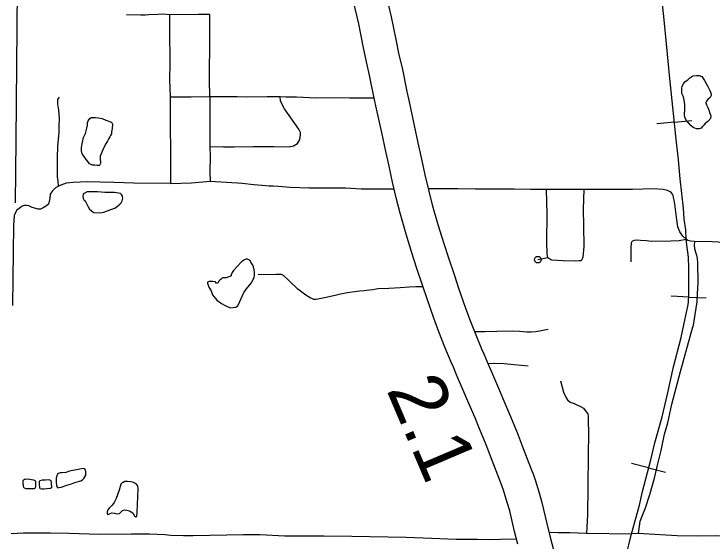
# Model space of a CAD drawing. Extents: x 61396 to 64680, y 55472 to 57605.
# Drawn here: x 62618.7 to 62782.6, y 56206.3 to 56330.1 of the extents above; entities that cross this region are included whole.
import ezdxf

# ---------------------------------------------------------------- set-up
doc = ezdxf.new("R2010")
doc.units = 0
for name, color, linetype in [('15', 7, 'Continuous'), ('33', 7, 'Continuous'), ('34', 7, 'Continuous'), ('35', 7, 'Continuous'), ('40', 7, 'Continuous'), ('48', 7, 'Continuous'), ('6', 7, 'Continuous')]:
    doc.layers.add(name, color=color, linetype=linetype)

msp = doc.modelspace()

# ---------------------------------------------------------------- linework, layer by layer
at = {"layer": '15'}
for points in [[(62706.06, 56334.76), (62707.32, 56329.4), (62708.41, 56324.06), (62709.1, 56320.51), (62709.85, 56317.42), (62710.97, 56311.87), (62711.49, 56309.45), (62712.72, 56303.87), (62713.58, 56299.82), (62714.43, 56295.95), (62715.19, 56292.28), (62716.07, 56288.8), (62716.93, 56285.29), (62718.28, 56280.6), (62719.64, 56276.15), (62720.67, 56273.01), (62722.16, 56268.65), (62723.13, 56265.69), (62724.66, 56261.25), (62725.77, 56258.25), (62727.17, 56254.77), (62728.54, 56251.45), (62729.08, 56250.26), (62729.86, 56248.39), (62731.57, 56244.37), (62732.49, 56242.23), (62734.18, 56238.3), (62735.11, 56236.08), (62736.87, 56231.81), (62738.31, 56228.06), (62740.19, 56223.16), (62740.69, 56221.86), (62741.12, 56220.66), (62742.02, 56217.63), (62742.71, 56215.39), (62743.83, 56210.41), (62744.58, 56207.56), (62745.86, 56202.44)], [(62737.02, 56205.61), (62736.24, 56208.55), (62735.16, 56213.38), (62734.54, 56215.37), (62733.69, 56218.24), (62733.37, 56219.15), (62732.9, 56220.35), (62731.02, 56225.26), (62729.61, 56228.92), (62727.9, 56233.08), (62726.99, 56235.24), (62725.31, 56239.15), (62724.38, 56241.31), (62722.67, 56245.35), (62721.92, 56247.12), (62721.37, 56248.34), (62719.93, 56251.82), (62718.48, 56255.44), (62717.3, 56258.62), (62715.72, 56263.21), (62714.75, 56266.17), (62713.27, 56270.53), (62712.19, 56273.79), (62710.79, 56278.37), (62709.38, 56283.28), (62708.49, 56286.91), (62707.57, 56290.54), (62706.79, 56294.32), (62705.94, 56298.17), (62705.08, 56302.23), (62703.86, 56307.79), (62703.32, 56310.27), (62702.22, 56315.73), (62701.47, 56318.86), (62700.75, 56322.54), (62699.69, 56327.72), (62698.46, 56332.97)]]:
    msp.add_lwpolyline(points, dxfattribs=at)
at = {"layer": '33'}
for p, q in [((62655.5, 56290.3), (62646.86, 56290.34)), ((62744.09, 56272.82), (62741.72, 56272.38)), ((62753.18, 56208.16), (62763.74, 56208)), ((62753.18, 56208.16), (62753.18, 56208.16)), ((62765.34, 56208.05), (62763.74, 56208))]:
    msp.add_line(p, q, dxfattribs=at)
for points in [[(62655.24, 56329.88), (62654.52, 56329.98), (62653.5, 56330.04), (62652.47, 56329.98), (62650.42, 56329.84), (62649.6, 56329.78), (62648.54, 56329.81), (62645.14, 56329.84)], [(62664.68, 56329.97), (62661.98, 56329.93), (62655.24, 56329.88)], [(62655.24, 56329.88), (62655.27, 56326.46), (62655.3, 56318.45), (62655.25, 56314.72), (62655.39, 56310.61)], [(62664.71, 56310.73), (62664.61, 56314.54), (62664.72, 56324.6), (62664.68, 56329.97)], [(62655.39, 56310.61), (62657.57, 56310.61), (62660.35, 56310.59), (62664.71, 56310.73)], [(62655.39, 56310.61), (62655.39, 56308.77), (62655.39, 56306.03), (62655.39, 56302.65), (62655.46, 56299.01), (62655.5, 56290.3)], [(62664.71, 56310.73), (62664.74, 56305.92), (62664.71, 56298.99)], [(62664.71, 56310.73), (62666.68, 56310.67), (62671.1, 56310.69), (62673.67, 56310.64), (62678.19, 56310.69), (62681.26, 56310.72)], [(62664.71, 56298.99), (62667.91, 56298.85), (62670.43, 56298.9), (62674.98, 56298.95), (62679.75, 56298.93), (62683.3, 56298.85), (62684.39, 56299.08), (62685.29, 56299.67), (62685.85, 56300.56), (62686.03, 56301.66), (62686.03, 56302.24), (62685.59, 56303.06), (62682.25, 56307.76), (62681.33, 56309.59), (62681.26, 56310.72)], [(62681.26, 56310.72), (62682.55, 56310.64), (62685.08, 56310.58), (62689.65, 56310.38), (62694.71, 56310.44), (62697.56, 56310.39), (62700.06, 56310.39), (62703.31, 56310.35)], [(62664.71, 56298.99), (62664.75, 56296.64), (62664.71, 56292.89), (62664.79, 56290.78)], [(62629.19, 56289.63), (62628.48, 56289.25), (62627.75, 56288.56), (62627.2, 56287.76), (62627.13, 56286.77), (62626.91, 56285.75), (62626.8, 56285.39), (62626.37, 56285.06), (62625.53, 56284.52), (62624.98, 56284.26), (62624.4, 56284.26), (62623.02, 56284.62), (62622.18, 56285.02), (62621.63, 56285.13), (62621.12, 56285.13), (62620.65, 56284.95), (62620.21, 56284.66), (62619.31, 56283.92), (62619.14, 56283.59), (62618.94, 56283.1)], [(62646.86, 56290.34), (62642.14, 56290.52), (62635.87, 56290.63), (62632.63, 56290.52), (62630.99, 56290.34), (62630.35, 56290.11), (62629.35, 56289.72), (62629.19, 56289.63)], [(62655.5, 56290.3), (62660.42, 56290.45), (62664.79, 56290.78)], [(62664.79, 56290.78), (62669.91, 56290.51), (62671.28, 56290.43), (62672.29, 56290.36), (62675.03, 56290.04), (62677.82, 56289.77), (62678.63, 56289.72), (62679.56, 56289.75), (62680.81, 56289.67), (62683.58, 56289.43), (62688.03, 56289.26), (62691.44, 56289.21), (62696.53, 56289.23), (62700.28, 56289), (62703.72, 56289), (62707.67, 56289.02), (62707.95, 56289.05)], [(62743.78, 56288.84), (62741.57, 56288.88), (62739.98, 56288.84), (62736.15, 56288.96), (62731.4, 56288.92), (62727.13, 56288.94), (62722.91, 56289.01), (62717.09, 56288.99), (62716.02, 56288.99)], [(62752.54, 56288.89), (62750.13, 56288.86), (62746.5, 56288.86), (62743.78, 56288.84)], [(62744.09, 56272.82), (62743.9, 56273.85), (62743.86, 56276.45), (62743.9, 56283.09), (62743.78, 56288.84)], [(62752.54, 56288.89), (62752.41, 56284.27), (62752.49, 56280.33), (62752.53, 56275.48), (62752.33, 56272.93), (62752.1, 56272.33), (62751.83, 56272.13), (62751.44, 56272.08), (62750.54, 56272.03), (62747.68, 56272.13), (62745.01, 56272.29), (62744.3, 56272.63), (62744.09, 56272.82)], [(62776.55, 56277.19), (62775.78, 56277.88), (62775.1, 56278.95), (62774.58, 56280.06), (62774.34, 56281.76), (62773.91, 56285.52), (62773.78, 56286.39), (62773.6, 56287.01), (62773.49, 56287.43), (62773.33, 56287.73), (62773.1, 56288.05), (62772.81, 56288.33), (62772.15, 56288.6), (62771.18, 56288.87), (62768.91, 56288.98), (62766.47, 56288.97), (62763.97, 56288.87), (62759.48, 56288.85), (62752.54, 56288.89)], [(62618.45, 56261.6), (62618.65, 56280.44), (62618.82, 56282.7), (62618.94, 56283.1)], [(62763.63, 56271.88), (62763.67, 56275.18), (62763.75, 56276.28), (62763.82, 56276.59), (62764.02, 56276.83), (62764.41, 56276.98), (62764.84, 56277.06), (62765.83, 56276.98), (62767.24, 56276.87), (62768.34, 56276.75), (62772.97, 56276.79), (62774.89, 56276.87), (62776.55, 56277.19)], [(62778.51, 56276.62), (62777.62, 56276.71), (62776.95, 56276.91), (62776.55, 56277.19)], [(62778.51, 56276.62), (62778.43, 56275.68), (62778.49, 56275.04), (62778.75, 56274.14), (62778.98, 56273.45), (62779.18, 56272.66), (62779.26, 56271.6), (62779.28, 56267.03), (62779.18, 56264.34), (62779.07, 56262.5), (62778.13, 56256.53)], [(62792.01, 56276.41), (62789.14, 56276.37), (62786.95, 56276.37), (62782.65, 56276.58), (62778.51, 56276.62)], [(62765.34, 56208.05), (62765.79, 56211.01), (62767.02, 56214.08), (62768.07, 56217.26), (62769.11, 56221.06), (62769.94, 56224.46), (62770.73, 56227.6), (62771.52, 56231.37), (62772.27, 56234.05), (62773.21, 56238.48), (62775.25, 56246.13), (62778.16, 56256.62)], [(62726.87, 56255.51), (62729.26, 56255.51), (62732.07, 56255.58), (62735.88, 56255.66), (62737.41, 56255.58), (62739.12, 56255.47), (62740.15, 56255.43), (62741.25, 56255.55), (62744.17, 56256.05)], [(62730.02, 56248.03), (62731.66, 56248.05), (62733.79, 56248.01), (62736.19, 56247.74), (62739.46, 56247.48)], [(62747.06, 56243.94), (62747.76, 56241.25), (62748.39, 56239.95), (62748.72, 56239.44), (62749.36, 56238.89), (62750.23, 56238.58), (62750.92, 56238.33), (62751.77, 56237.89), (62752.45, 56237.5)], [(62752.45, 56237.5), (62753.1, 56236.68), (62753.44, 56236.17), (62753.54, 56235.56), (62753.54, 56234.76), (62753.64, 56231.4), (62753.56, 56226.73), (62753.46, 56219.06), (62753.36, 56212.52), (62753.21, 56209.55), (62753.18, 56208.16)], [(62618.07, 56208.06), (62620.84, 56208.26), (62627.26, 56208.26), (62631.69, 56208.16), (62638.73, 56207.92), (62646.35, 56208), (62650.56, 56208.02), (62654.11, 56207.81), (62655.57, 56207.7), (62658.51, 56207.62), (62660.83, 56207.65), (62672.64, 56207.84), (62676.45, 56207.84), (62682.34, 56207.54), (62691.51, 56207.52), (62698.07, 56207.49), (62710.8, 56207.23), (62716.75, 56206.98), (62722.53, 56206.75), (62727.57, 56206.72), (62730.31, 56206.66), (62732.93, 56206.72), (62736.7, 56206.82)], [(62753.18, 56208.09), (62749.25, 56208.21), (62746.5, 56208.25), (62744.39, 56208.29)], [(62799.01, 56207.06), (62796.81, 56207.26), (62792.65, 56207.23), (62783.72, 56207.53), (62779.21, 56207.46), (62774.49, 56207.57), (62766.57, 56208), (62765.34, 56208.05)]]:
    msp.add_lwpolyline(points, dxfattribs=at)
msp.add_circle((62741.72, 56272.38), 0.781, dxfattribs=at)
at = {"layer": '34'}
for points in [[(62629.19, 56289.63), (62629.07, 56290.87), (62628.97, 56291.75), (62628.92, 56294.5), (62628.91, 56296.36), (62629.05, 56298.94), (62629.35, 56302.34), (62629.36, 56303.72), (62629.38, 56305.53), (62629.33, 56306.58), (62629.24, 56307.43), (62629.14, 56308.12), (62629.05, 56308.74), (62629.02, 56309.03), (62629.02, 56309.39), (62629.02, 56309.65), (62629.05, 56309.98), (62629.17, 56310.19), (62629.4, 56310.5)], [(62714.82, 56265.98), (62713.05, 56265.98), (62711.53, 56265.93), (62709.39, 56265.76), (62706.76, 56265.59), (62704.21, 56265.5), (62702.91, 56265.3), (62700.93, 56265.04), (62699.92, 56264.97), (62699.29, 56264.87), (62697, 56264.56), (62695.39, 56264.27), (62694.11, 56263.96), (62691.63, 56263.4), (62690.45, 56263.21), (62690.04, 56263.14), (62689.63, 56263.06), (62689.42, 56263.04), (62689.13, 56263.06), (62688.81, 56263.16), (62688.28, 56263.43), (62687.27, 56264.05), (62685.39, 56265.43), (62683.15, 56267.59), (62682.04, 56268.63), (62681.56, 56268.87), (62681.18, 56268.89), (62680.91, 56268.89), (62680.21, 56268.89), (62676.02, 56268.8)]]:
    msp.add_lwpolyline(points, dxfattribs=at)
at = {"layer": '35'}
for points in [[(62776.96, 56314.6), (62777.44, 56315.08), (62778.17, 56315.53), (62779, 56315.64), (62779.65, 56315.6), (62780.28, 56315.36), (62780.9, 56314.43), (62781.69, 56313.01), (62782.14, 56312.08), (62782.31, 56311.73), (62782.45, 56311.25), (62782.42, 56310.9), (62782.18, 56310.46), (62781.66, 56309.97), (62781.35, 56309.63), (62781.21, 56309.32), (62781.21, 56309.18), (62781.31, 56308.73), (62781.66, 56308.14), (62781.97, 56307.31), (62782.07, 56306.93), (62782.25, 56306.42), (62782.35, 56305.97), (62782.31, 56305.55), (62781.62, 56304.79), (62781.07, 56304.34), (62780.73, 56303.93), (62780.41, 56303.62), (62780.1, 56303.27), (62779.65, 56303.07), (62779, 56303.1), (62778.2, 56303.41), (62777.65, 56303.86), (62777.1, 56304.52), (62776.58, 56305.17), (62776.24, 56305.83), (62776.2, 56306.45), (62776.24, 56307.62), (62776.24, 56308.83), (62776.1, 56309.8), (62775.92, 56310.59), (62775.61, 56311.22), (62775.54, 56311.66), (62775.54, 56312.63), (62775.65, 56313.12), (62775.92, 56313.7), (62776.34, 56314.22)], [(62637.5, 56283.48), (62638.95, 56283.4), (62639.85, 56283.53), (62641.45, 56284.13), (62642.38, 56284.51), (62643.05, 56284.95), (62643.56, 56285.39), (62643.87, 56285.75), (62644.11, 56286.16), (62644.23, 56286.52), (62644.26, 56286.86), (62644.21, 56287.32), (62643.98, 56287.69), (62643.72, 56287.94), (62642.33, 56288.12), (62641.22, 56288.12), (62640.6, 56288.12), (62640.03, 56288.15), (62638.3, 56288.28), (62636.57, 56288.28), (62635.88, 56288.28), (62635.18, 56287.94), (62634.97, 56287.76), (62634.92, 56287.3), (62634.95, 56286.78), (62635.08, 56286.4), (62635.33, 56286.16), (62635.57, 56285.88), (62635.8, 56285.39), (62636.11, 56284.8), (62636.47, 56284.25), (62636.93, 56283.82), (62637.24, 56283.58)], [(62670.78, 56261.2), (62671.26, 56261.54), (62671.74, 56262.54), (62672.36, 56263.95), (62672.7, 56264.64), (62673.08, 56265.19), (62673.67, 56265.95), (62674.49, 56266.98), (62674.87, 56267.77), (62675.08, 56268.08), (62675.15, 56268.25), (62675.18, 56268.6), (62675.22, 56269.39), (62675.08, 56270.01), (62674.98, 56270.66), (62674.77, 56271.11), (62674.36, 56271.83), (62674.15, 56272.18), (62673.7, 56272.45), (62673.43, 56272.56), (62672.88, 56272.38), (62672.12, 56271.9), (62671.09, 56270.8), (62670.23, 56269.87), (62669.99, 56269.39), (62669.74, 56268.84), (62669.68, 56268.56), (62669.4, 56268.39), (62669.16, 56268.32), (62668.57, 56268.12), (62668.06, 56268.15), (62667.68, 56268.15), (62667.37, 56267.81), (62667.09, 56267.57), (62666.78, 56267.22), (62666.72, 56267.08), (62666.61, 56266.91), (62666.41, 56266.84), (62666.23, 56266.84), (62666.13, 56266.88), (62666.03, 56267.15), (62665.44, 56267.26), (62664.99, 56267.26), (62664.55, 56267.26), (62664.17, 56267.12), (62664.13, 56266.88), (62664.51, 56265.91), (62664.99, 56265.05), (62665.34, 56264.12), (62666.34, 56262.89), (62667.47, 56262.09), (62668.33, 56261.61), (62669.47, 56261.1)], [(62629.77, 56218.93), (62631.09, 56219.41), (62632.21, 56219.78), (62632.97, 56220.06), (62633.53, 56220.25), (62634.07, 56220.34), (62634.38, 56220.45), (62634.83, 56220.67), (62635.13, 56220.98), (62635.39, 56221.4), (62635.56, 56221.8), (62635.58, 56222.16), (62635.61, 56222.61), (62635.42, 56223.14), (62635.22, 56223.23), (62634.94, 56223.31), (62633.76, 56223.14), (62631.79, 56222.75), (62630.87, 56222.44), (62629.88, 56222.36), (62629.58, 56222.33), (62629.13, 56222.19), (62628.9, 56221.99), (62628.79, 56221.66), (62628.59, 56221.1), (62628.59, 56220.25), (62628.73, 56219.38), (62628.87, 56218.99), (62629.01, 56218.82), (62629.27, 56218.88)], [(62621.39, 56220.83), (62622.06, 56220.93), (62622.85, 56220.78), (62623.29, 56220.69), (62623.61, 56220.56), (62623.76, 56220.39), (62623.76, 56220.17), (62623.76, 56219.23), (62623.66, 56218.79), (62623.59, 56218.66), (62623.44, 56218.59), (62622.97, 56218.59), (62622.21, 56218.61), (62621.54, 56218.61), (62621.2, 56218.71), (62621.05, 56218.86), (62620.95, 56219.16), (62620.92, 56219.4), (62620.88, 56219.8), (62620.9, 56220.09), (62620.9, 56220.49), (62621, 56220.71), (62621.12, 56220.81)], [(62624.87, 56220.56), (62625.41, 56220.66), (62626.08, 56220.69), (62626.77, 56220.73), (62627.02, 56220.71), (62627.29, 56220.61), (62627.39, 56220.49), (62627.44, 56219.97), (62627.49, 56218.84), (62627.31, 56218.64), (62627.14, 56218.64), (62626.45, 56218.54), (62625.73, 56218.47), (62625.24, 56218.49), (62624.9, 56218.61), (62624.82, 56218.76), (62624.75, 56219.06), (62624.7, 56219.48), (62624.7, 56219.95), (62624.7, 56220.34), (62624.82, 56220.49)], [(62647.32, 56212.02), (62647.55, 56212.07), (62647.58, 56212.24), (62647.63, 56212.98), (62647.86, 56218.68), (62647.83, 56219.19), (62647.71, 56219.37), (62647.38, 56219.73), (62647.22, 56219.8), (62646.82, 56220.03), (62646.2, 56220.18), (62645.39, 56220.29), (62644.78, 56220.26), (62644.37, 56220.08), (62644.09, 56219.98), (62643.81, 56219.65), (62643.38, 56218.28), (62642.74, 56216.32), (62642.23, 56215.4), (62641.72, 56214.66), (62641.39, 56214.38), (62641.09, 56214.03), (62640.78, 56213.64), (62640.58, 56213.14), (62640.63, 56212.73), (62640.73, 56212.55), (62640.96, 56212.63), (62641.32, 56212.75), (62641.67, 56212.91), (62642.31, 56212.86), (62642.59, 56212.8), (62642.97, 56212.73), (62643.46, 56212.78), (62643.76, 56213.03), (62643.94, 56213.24), (62644.22, 56213.47), (62644.73, 56213.67), (62645.21, 56213.54), (62645.82, 56213.42), (62646.23, 56213.21), (62646.59, 56212.93), (62646.71, 56212.73), (62646.84, 56212.45), (62647.04, 56212.19), (62647.07, 56212.14)]]:
    msp.add_lwpolyline(points, close=True, dxfattribs=at)
for points in [[(62641.86, 56304.19), (62641.77, 56303.16), (62641.64, 56302.37), (62641.61, 56301.95), (62641.4, 56301.5), (62641.19, 56301.19), (62640.95, 56300.8), (62640.7, 56300.22), (62640.19, 56299.49), (62639.61, 56298.16), (62638.95, 56296.71), (62638.98, 56295.92), (62639.04, 56295.34), (62639.01, 56294.95), (62638.89, 56294.61), (62638.7, 56294.52), (62638.16, 56294.52), (62637.64, 56294.55), (62637.13, 56294.58), (62636.82, 56294.74), (62636.43, 56294.89), (62636.13, 56295.34), (62635.67, 56295.89), (62635.16, 56296.62), (62634.73, 56297.25), (62634.55, 56297.95), (62634.55, 56298.74), (62634.79, 56299.95), (62635.07, 56301.07), (62635.49, 56302.01), (62635.82, 56303.28), (62635.94, 56303.95), (62636.01, 56304.53), (62636.16, 56304.98), (62636.52, 56305.56), (62636.85, 56305.74)], [(62636.85, 56305.74), (62637.82, 56305.74), (62638.58, 56305.65), (62639.43, 56305.5), (62640.28, 56305.13), (62641.64, 56304.65), (62641.86, 56304.19)]]:
    msp.add_lwpolyline(points, dxfattribs=at)
at = {"layer": '40'}
for p, q in [((62773.82, 56304.67), (62769.72, 56304.24)), ((62773.82, 56304.67), (62777.93, 56305.09)), ((62777.18, 56263.6), (62773.06, 56263.81)), ((62777.18, 56263.6), (62781.3, 56263.39)), ((62767.75, 56223.48), (62763.75, 56224.5)), ((62767.75, 56223.48), (62771.74, 56222.46))]:
    msp.add_line(p, q, dxfattribs=at)
for points in [[(62776.55, 56277.19), (62776.5, 56279.36), (62776.12, 56281.92), (62775.92, 56284.47), (62775.14, 56291.4), (62774.79, 56295.84), (62774.17, 56301.39), (62773.61, 56306.69), (62772.72, 56314.93), (62771.95, 56323.03), (62771.37, 56328.69), (62770.81, 56334.62), (62770.37, 56338.57), (62769.88, 56342.08), (62769.55, 56345.85), (62769.06, 56351.43), (62767.95, 56362.08), (62767.19, 56368.41)], [(62763.12, 56205.44), (62763.74, 56208), (62765.59, 56214.72), (62766.33, 56217.94), (62768.24, 56225.39), (62769.19, 56229.41), (62770.9, 56235.5), (62772.17, 56240.8), (62773.63, 56247.24), (62775.37, 56254.08), (62776.03, 56257.1), (62776.76, 56260.34), (62776.96, 56261.45), (62777.12, 56262.36), (62777.23, 56264.53), (62777.23, 56270.28), (62777.1, 56272.97), (62776.74, 56275.9), (62776.55, 56277.19), (62776.5, 56279.36), (62776.12, 56281.92), (62775.92, 56284.47), (62775.14, 56291.4), (62774.79, 56295.84), (62774.17, 56301.39), (62773.61, 56306.69), (62772.72, 56314.93), (62771.95, 56323.03), (62771.37, 56328.69), (62770.81, 56334.62)], [(62763.74, 56208), (62765.59, 56214.72), (62766.33, 56217.94), (62768.24, 56225.39), (62769.19, 56229.41), (62770.9, 56235.5), (62772.17, 56240.8), (62773.63, 56247.24), (62775.37, 56254.08), (62776.03, 56257.1), (62776.76, 56260.34), (62776.96, 56261.45), (62777.12, 56262.36), (62777.23, 56264.53), (62777.23, 56270.28), (62777.1, 56272.97), (62776.74, 56275.9), (62776.55, 56277.19)], [(62752.79, 56165.19), (62754.04, 56168.98), (62756.12, 56176.94), (62757.5, 56182.81), (62758.92, 56188.85), (62763.12, 56205.44), (62763.74, 56208)]]:
    msp.add_lwpolyline(points, dxfattribs=at)
at = {"layer": '6'}
msp.add_lwpolyline([(62619.66, 56359.73), (62619.6, 56353.58), (62619.11, 56300.4), (62618.97, 56285.69)], dxfattribs=at)

# ---------------------------------------------------------------- texts
at = {"layer": '48'}
msp.add_text('2.1', height=13.2, rotation=293.0546, dxfattribs=at).set_placement((62706.11, 56241.87))

doc.saveas('drawing.dxf')
